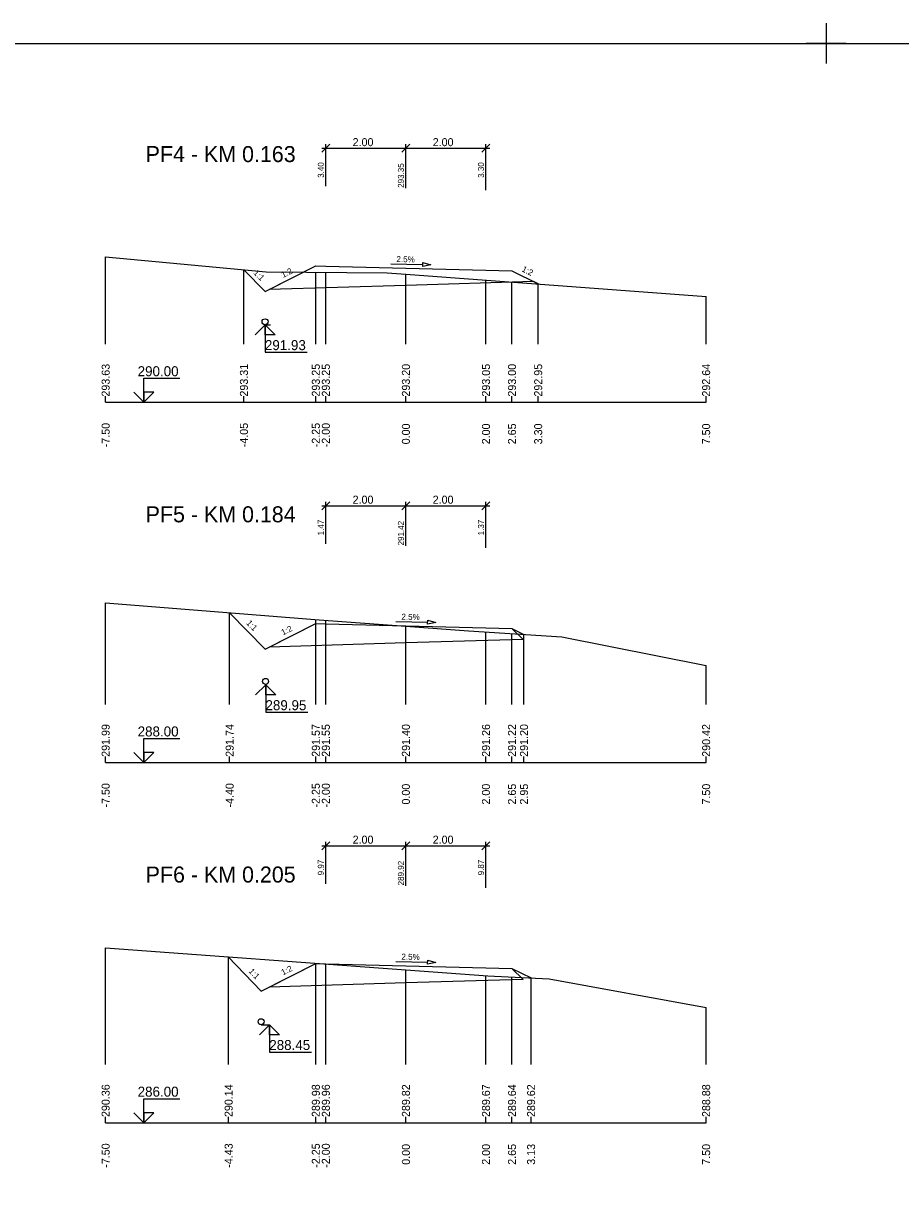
# Model space of a CAD drawing. Extents: x -5 to 1895, y -2 to 602.
# Drawn here: x 219.4 to 438.6, y 310.3 to 601.7 of the extents above; entities that cross this region are included whole.
import ezdxf

# ---------------------------------------------------------------- set-up
doc = ezdxf.new("R2010")
doc.units = 0
for name, color, linetype in [('KOTA', 7, 'Continuous'), ('KOTA_DELKY', 7, 'Continuous'), ('KOTA_DELKY_CONT', 7, 'Continuous'), ('KRIZENI', 7, 'Continuous'), ('NS_TELESO_VOZOVKY', 7, 'Continuous'), ('NS_V_PF', 7, 'Continuous'), ('REZY_PF_PUVODNI', 7, 'Continuous'), ('SESTAVY_REZU_PF', 7, 'Continuous'), ('SKLON', 7, 'Continuous'), ('SVK', 7, 'Continuous')]:
    doc.layers.add(name, color=color, linetype=linetype)

msp = doc.modelspace()

# ---------------------------------------------------------------- linework, layer by layer
for p, q in [((420, 601.67), (420, 591.67)), ((420, 601.67), (420, 591.67)), ((420, 601.67), (420, 591.67)), ((420, 601.67), (420, 591.67)), ((420, 601.67), (420, 591.67)), ((420, 601.67), (420, 591.67)), ((420, 601.67), (420, 591.67)), ((420, 601.67), (420, 591.67)), ((420, 601.67), (420, 591.67)), ((420, 601.67), (420, 591.67)), ((420, 601.67), (420, 591.67)), ((420, 601.67), (420, 591.67)), ((420, 601.67), (420, 591.67)), ((420, 601.67), (420, 591.67)), ((420, 601.67), (420, 591.67)), ((420, 601.67), (420, 591.67)), ((420, 601.67), (420, 591.67)), ((420, 601.67), (420, 591.67)), ((420, 601.67), (420, 591.67)), ((420, 601.67), (420, 591.67)), ((420, 601.67), (420, 591.67)), ((420, 601.67), (420, 591.67)), ((420, 601.67), (420, 591.67)), ((420, 601.67), (420, 591.67)), ((420, 601.67), (420, 591.67)), ((420, 601.67), (420, 591.67)), ((420, 601.67), (420, 591.67)), ((420, 601.67), (420, 591.67)), ((420, 601.67), (420, 591.67)), ((420, 601.67), (420, 591.67)), ((420, 601.67), (420, 591.67)), ((420, 601.67), (420, 591.67)), ((420, 601.67), (420, 591.67)), ((420, 601.67), (420, 591.67)), ((420, 601.67), (420, 591.67)), ((420, 601.67), (420, 591.67)), ((420, 601.67), (420, 591.67)), ((420, 601.67), (420, 591.67)), ((420, 601.67), (420, 591.67)), ((420, 601.67), (420, 591.67)), ((420, 601.67), (420, 591.67)), ((420, 601.67), (420, 591.67)), ((420, 601.67), (420, 591.67)), ((420, 601.67), (420, 591.67)), ((420, 601.67), (420, 591.67)), ((420, 601.67), (420, 591.67)), ((420, 601.67), (420, 591.67)), ((420, 601.67), (420, 591.67)), ((420, 601.67), (420, 591.67)), ((420, 601.67), (420, 591.67)), ((420, 601.67), (420, 591.67)), ((420, 601.67), (420, 591.67)), ((420, 601.67), (420, 591.67)), ((420, 601.67), (420, 591.67)), ((425, 596.67), (415, 596.67)), ((425, 596.67), (415, 596.67)), ((425, 596.67), (415, 596.67)), ((425, 596.67), (415, 596.67)), ((425, 596.67), (415, 596.67)), ((425, 596.67), (415, 596.67)), ((425, 596.67), (415, 596.67)), ((425, 596.67), (415, 596.67)), ((425, 596.67), (415, 596.67)), ((425, 596.67), (415, 596.67)), ((425, 596.67), (415, 596.67)), ((425, 596.67), (415, 596.67)), ((425, 596.67), (415, 596.67)), ((425, 596.67), (415, 596.67)), ((425, 596.67), (415, 596.67)), ((425, 596.67), (415, 596.67)), ((425, 596.67), (415, 596.67)), ((425, 596.67), (415, 596.67)), ((425, 596.67), (415, 596.67)), ((425, 596.67), (415, 596.67)), ((425, 596.67), (415, 596.67)), ((425, 596.67), (415, 596.67)), ((425, 596.67), (415, 596.67)), ((425, 596.67), (415, 596.67)), ((425, 596.67), (415, 596.67)), ((425, 596.67), (415, 596.67)), ((425, 596.67), (415, 596.67)), ((425, 596.67), (415, 596.67)), ((425, 596.67), (415, 596.67)), ((425, 596.67), (415, 596.67)), ((425, 596.67), (415, 596.67)), ((425, 596.67), (415, 596.67)), ((425, 596.67), (415, 596.67)), ((425, 596.67), (415, 596.67)), ((425, 596.67), (415, 596.67)), ((425, 596.67), (415, 596.67)), ((425, 596.67), (415, 596.67)), ((425, 596.67), (415, 596.67)), ((425, 596.67), (415, 596.67)), ((425, 596.67), (415, 596.67)), ((425, 596.67), (415, 596.67)), ((425, 596.67), (415, 596.67)), ((425, 596.67), (415, 596.67)), ((425, 596.67), (415, 596.67)), ((425, 596.67), (415, 596.67)), ((425, 596.67), (415, 596.67)), ((425, 596.67), (415, 596.67)), ((425, 596.67), (415, 596.67)), ((425, 596.67), (415, 596.67)), ((425, 596.67), (415, 596.67)), ((425, 596.67), (415, 596.67)), ((425, 596.67), (415, 596.67)), ((425, 596.67), (415, 596.67)), ((425, 596.67), (415, 596.67))]:
    msp.add_line(p, q)
msp.add_lwpolyline([(0, 596.67), (1890, 596.67), (1890, 2.67), (0, 2.67)], close=True)
at = {"layer": 'KOTA'}
for points in [[(279.82, 526.35), (277.32, 523.85), (279.82, 526.35), (279.82, 519.52), (290.37, 519.52)], [(279.82, 526.35), (281.19, 526.35)], [(279.82, 526.35), (282.32, 523.85), (279.82, 523.85), (279.82, 526.35)], [(279.82, 526.35), (282.32, 523.85), (279.82, 523.85)], [(249.57, 507), (247.07, 509.5), (249.57, 507), (249.57, 513), (258.57, 513)], [(249.57, 507), (252.07, 509.5), (249.57, 509.5), (249.57, 507)], [(249.57, 507), (252.07, 509.5), (249.57, 509.5)], [(279.97, 436.38), (277.47, 433.88), (279.97, 436.38), (279.97, 429.56), (290.51, 429.56)], [(279.97, 436.38), (282.47, 433.88), (279.97, 433.88), (279.97, 436.38)], [(279.97, 436.38), (282.47, 433.88), (279.97, 433.88)], [(249.57, 417), (247.07, 419.5), (249.57, 417), (249.57, 423), (258.57, 423)], [(249.57, 417), (252.07, 419.5), (249.57, 419.5), (249.57, 417)], [(249.57, 417), (252.07, 419.5), (249.57, 419.5)], [(280.92, 351.48), (278.42, 348.98), (280.92, 351.48), (280.92, 344.66), (291.46, 344.66)], [(278.83, 351.48), (280.92, 351.48)], [(280.92, 351.48), (283.42, 348.98), (280.92, 348.98), (280.92, 351.48)], [(280.92, 351.48), (283.42, 348.98), (280.92, 348.98)], [(249.57, 327), (247.07, 329.5), (249.57, 327), (249.57, 333), (258.57, 333)], [(249.57, 327), (252.07, 329.5), (249.57, 329.5), (249.57, 327)], [(249.57, 327), (252.07, 329.5), (249.57, 329.5)]]:
    msp.add_lwpolyline(points, dxfattribs=at)
at = {"layer": 'KOTA_DELKY'}
for points in [[(294, 569.48), (296, 571.48)], [(295, 560.98), (295, 571.48)], [(314, 569.48), (316, 571.48)], [(314, 569.48), (316, 571.48)], [(315, 560.48), (315, 571.48)], [(315, 560.48), (315, 571.48)], [(334, 569.48), (336, 571.48)], [(335, 559.98), (335, 571.48)], [(294, 570.48), (316, 570.48)], [(314, 570.48), (336, 570.48)], [(294, 480.15), (296, 482.15)], [(294, 481.15), (316, 481.15)], [(295, 471.65), (295, 482.15)], [(314, 480.15), (316, 482.15)], [(314, 480.15), (316, 482.15)], [(314, 481.15), (336, 481.15)], [(315, 471.15), (315, 482.15)], [(315, 471.15), (315, 482.15)], [(334, 480.15), (336, 482.15)], [(335, 470.65), (335, 482.15)], [(294, 395.21), (296, 397.21)], [(295, 386.71), (295, 397.21)], [(314, 395.21), (316, 397.21)], [(314, 395.21), (316, 397.21)], [(315, 386.21), (315, 397.21)], [(315, 386.21), (315, 397.21)], [(334, 395.21), (336, 397.21)], [(335, 385.71), (335, 397.21)], [(294, 396.21), (316, 396.21)], [(314, 396.21), (336, 396.21)]]:
    msp.add_lwpolyline(points, dxfattribs=at)
at = {"layer": 'KRIZENI'}
for centre in [(279.82, 527.1), (279.94, 437.25), (278.83, 352.23)]:
    msp.add_circle(centre, 0.75, dxfattribs=at)
at = {"layer": 'NS_TELESO_VOZOVKY'}
for points in [[(315, 540.48), (335, 539.98), (341.5, 539.82), (348.04, 536.55), (346.86, 537.14), (315, 536.18), (280.83, 535.16), (292.5, 541.04), (295, 540.98), (315, 540.48)], [(315, 451.15), (335, 450.65), (341.5, 450.49), (344.26, 447.73), (315, 446.85), (280.83, 445.83), (292.5, 451.71), (295, 451.65), (315, 451.15)], [(315, 366.21), (335, 365.71), (341.5, 365.55), (344.26, 362.79), (315, 361.91), (280.82, 360.89), (292.5, 366.77), (295, 366.71), (315, 366.21)]]:
    msp.add_lwpolyline(points, dxfattribs=at)
at = {"layer": 'NS_V_PF'}
for points in [[(274.54, 540.11), (279.87, 534.67), (292.5, 541.04), (295, 540.98), (315, 540.48), (335, 539.98), (341.5, 539.82), (348.04, 536.55)], [(270.97, 454.42), (279.87, 445.34), (292.5, 451.71), (295, 451.65), (315, 451.15), (335, 450.65), (341.5, 450.49), (344.5, 448.99)], [(270.64, 368.42), (278.85, 359.9), (292.5, 366.77), (295, 366.71), (315, 366.21), (335, 365.71), (341.5, 365.55), (346.27, 363.16)]]:
    msp.add_lwpolyline(points, dxfattribs=at)
at = {"layer": 'REZY_PF_PUVODNI'}
for points in [[(240, 543.34), (280.06, 539.59), (310.35, 539.37), (315, 539.02), (390, 533.41)], [(240, 456.87), (293.33, 452.65), (315, 451.05), (315, 451.05), (330.64, 449.89), (353.95, 448.37), (390, 441.21)], [(240, 370.65), (315, 365.19), (335.5, 363.7), (350.76, 362.94), (390, 355.77)]]:
    msp.add_lwpolyline(points, dxfattribs=at)
at = {"layer": 'SESTAVY_REZU_PF'}
for points in [[(240, 507), (390, 507)], [(240, 417), (390, 417)], [(240, 327), (390, 327)]]:
    msp.add_lwpolyline(points, dxfattribs=at)
at = {"layer": 'SKLON'}
for points in [[(311.21, 541.58), (319.21, 541.38)], [(319.22, 541.88), (321.21, 541.33), (319.2, 540.88), (319.22, 541.88)], [(312.45, 452.22), (320.45, 452.02)], [(320.46, 452.52), (322.45, 451.97), (320.43, 451.52), (320.46, 452.52)], [(312.45, 367.28), (320.45, 367.08)], [(320.46, 367.58), (322.45, 367.03), (320.43, 366.58), (320.46, 367.58)]]:
    msp.add_lwpolyline(points, dxfattribs=at)
for points in [[(319.22, 541.88), (321.21, 541.33), (319.2, 540.88)], [(320.46, 452.52), (322.45, 451.97), (320.43, 451.52)], [(320.46, 367.58), (322.45, 367.03), (320.43, 366.58)]]:
    msp.add_lwpolyline(points, close=True, dxfattribs=at)
at = {"layer": 'SVK'}
for points in [[(240, 521.5), (240, 543.34)], [(274.54, 521.5), (274.54, 540.11)], [(292.5, 521.5), (292.5, 539.5)], [(295, 521.5), (295, 539.48)], [(315, 521.5), (315, 539.02)], [(335, 521.5), (335, 537.52)], [(341.5, 521.5), (341.5, 537.04)], [(348.04, 521.5), (348.04, 536.55)], [(390, 521.5), (390, 533.41)], [(240, 507), (240, 508.5)], [(274.54, 507), (274.54, 508.5)], [(292.5, 507), (292.5, 508.5)], [(295, 507), (295, 508.5)], [(315, 507), (315, 508.5)], [(335, 507), (335, 508.5)], [(341.5, 507), (341.5, 508.5)], [(348.04, 507), (348.04, 508.5)], [(390, 507), (390, 508.5)], [(240, 431.5), (240, 456.87)], [(270.97, 431.5), (270.97, 454.42)], [(292.5, 431.5), (292.5, 452.72)], [(295, 431.5), (295, 452.53)], [(315, 431.5), (315, 451.05)], [(335, 431.5), (335, 449.61)], [(341.5, 431.5), (341.5, 449.18)], [(344.5, 431.5), (344.5, 448.99)], [(390, 431.5), (390, 441.21)], [(240, 417), (240, 418.5)], [(270.97, 417), (270.97, 418.5)], [(292.5, 417), (292.5, 418.5)], [(295, 417), (295, 418.5)], [(315, 417), (315, 418.5)], [(335, 417), (335, 418.5)], [(341.5, 417), (341.5, 418.5)], [(344.5, 417), (344.5, 418.5)], [(390, 417), (390, 418.5)], [(240, 341.5), (240, 370.65)], [(270.72, 341.5), (270.72, 368.41)], [(292.5, 341.5), (292.5, 366.83)], [(295, 341.5), (295, 366.64)], [(315, 341.5), (315, 365.19)], [(335, 341.5), (335, 363.73)], [(341.5, 341.5), (341.5, 363.4)], [(346.27, 341.5), (346.27, 363.16)], [(390, 341.5), (390, 355.77)], [(240, 327), (240, 328.5)], [(270.72, 327), (270.72, 328.5)], [(292.5, 327), (292.5, 328.5)], [(295, 327), (295, 328.5)], [(315, 327), (315, 328.5)], [(335, 327), (335, 328.5)], [(341.5, 327), (341.5, 328.5)], [(346.27, 327), (346.27, 328.5)], [(390, 327), (390, 328.5)]]:
    msp.add_lwpolyline(points, dxfattribs=at)

# ---------------------------------------------------------------- texts
at = {"layer": 'KOTA'}
for s, p in [('291.93', (279.78, 520.02)), ('290.00', (247.99, 513.5)), ('289.95', (279.92, 430.06)), ('288.00', (247.99, 423.5)), ('288.45', (280.87, 345.16)), ('286.00', (247.99, 333.5))]:
    msp.add_text(s, height=2.5, dxfattribs=at).set_placement(p)
at = {"layer": 'KOTA_DELKY'}
for p in [(301.69, 570.98), (321.69, 570.98), (301.69, 481.65), (321.69, 481.65), (301.69, 396.71), (321.69, 396.71)]:
    msp.add_text('2.00', height=2, dxfattribs=at).set_placement(p)
at = {"layer": 'KOTA_DELKY_CONT'}
for s, p in [('3.40', (294.5, 563.07)), ('293.35', (314.5, 560.56)), ('3.30', (334.5, 563.07)), ('1.47', (294.5, 473.74)), ('291.42', (314.5, 471.23)), ('1.37', (334.5, 473.74)), ('9.97', (294.5, 388.8)), ('289.92', (314.5, 386.29)), ('9.87', (334.5, 388.8))]:
    msp.add_text(s, height=1.5, rotation=90, dxfattribs=at).set_placement(p)
at = {"layer": 'SESTAVY_REZU_PF'}
for s, p in [('PF4 - KM 0.163', (250, 567)), ('PF5 - KM 0.184', (250, 477)), ('PF6 - KM 0.205', (250, 387))]:
    msp.add_text(s, height=4, dxfattribs=at).set_placement(p)
at = {"layer": 'SKLON'}
for s, rotation, p in [('2.5%', 358.5679, (312.63, 542.04)), ('1:1', 314.4213, (276.81, 539.21)), ('1:2', 26.7649, (284.32, 538.04)), ('1:2', 333.4349, (343.81, 539.78)), ('1:1', 314.4213, (275.03, 451.71)), ('2.5%', 358.5679, (313.87, 452.68)), ('1:2', 26.7649, (284.32, 448.71)), ('2.5%', 358.5679, (313.87, 367.74)), ('1:1', 313.9573, (275.62, 364.7)), ('1:2', 26.7501, (284.32, 363.77))]:
    msp.add_text(s, height=1.5, rotation=rotation, dxfattribs=at).set_placement(p)
at = {"layer": 'SVK'}
for s, p in [(' 293.63', (241, 507.67)), (' 293.31', (275.54, 507.67)), (' 293.25', (293.5, 507.67)), (' 293.25', (296, 507.67)), (' 293.20', (316, 507.67)), (' 293.05', (336, 507.67)), (' 293.00', (342.5, 507.67)), (' 292.95', (349.04, 507.67)), (' 292.64', (391, 507.67)), (' -7.50', (241, 495)), (' -4.05', (275.54, 495)), (' -2.25', (293.5, 495)), (' -2.00', (296, 495)), ('  0.00', (316, 495)), ('  2.00', (336, 495)), ('  2.65', (342.5, 495)), ('  3.30', (349.04, 495)), ('  7.50', (391, 495)), (' 291.99', (241, 417.67)), (' 291.74', (271.97, 417.67)), (' 291.57', (293.5, 417.67)), (' 291.55', (296, 417.67)), (' 291.40', (316, 417.67)), (' 291.26', (336, 417.67)), (' 291.22', (342.5, 417.67)), (' 291.20', (345.5, 417.67)), (' 290.42', (391, 417.67)), (' -7.50', (241, 405)), (' -4.40', (271.97, 405)), (' -2.25', (293.5, 405)), (' -2.00', (296, 405)), ('  0.00', (316, 405)), ('  2.00', (336, 405)), ('  2.65', (342.5, 405)), ('  2.95', (345.5, 405)), ('  7.50', (391, 405)), (' 290.36', (241, 327.67)), (' 290.14', (271.72, 327.67)), (' 289.98', (293.5, 327.67)), (' 289.96', (296, 327.67)), (' 289.82', (316, 327.67)), (' 289.67', (336, 327.67)), (' 289.64', (342.5, 327.67)), (' 289.62', (347.27, 327.67)), (' 288.88', (391, 327.67)), (' -7.50', (241, 315)), (' -4.43', (271.72, 315)), (' -2.25', (293.5, 315)), (' -2.00', (296, 315)), ('  0.00', (316, 315)), ('  2.00', (336, 315)), ('  2.65', (342.5, 315)), ('  3.13', (347.27, 315)), ('  7.50', (391, 315))]:
    msp.add_text(s, height=2, rotation=90, dxfattribs=at).set_placement(p)

doc.saveas('drawing.dxf')
